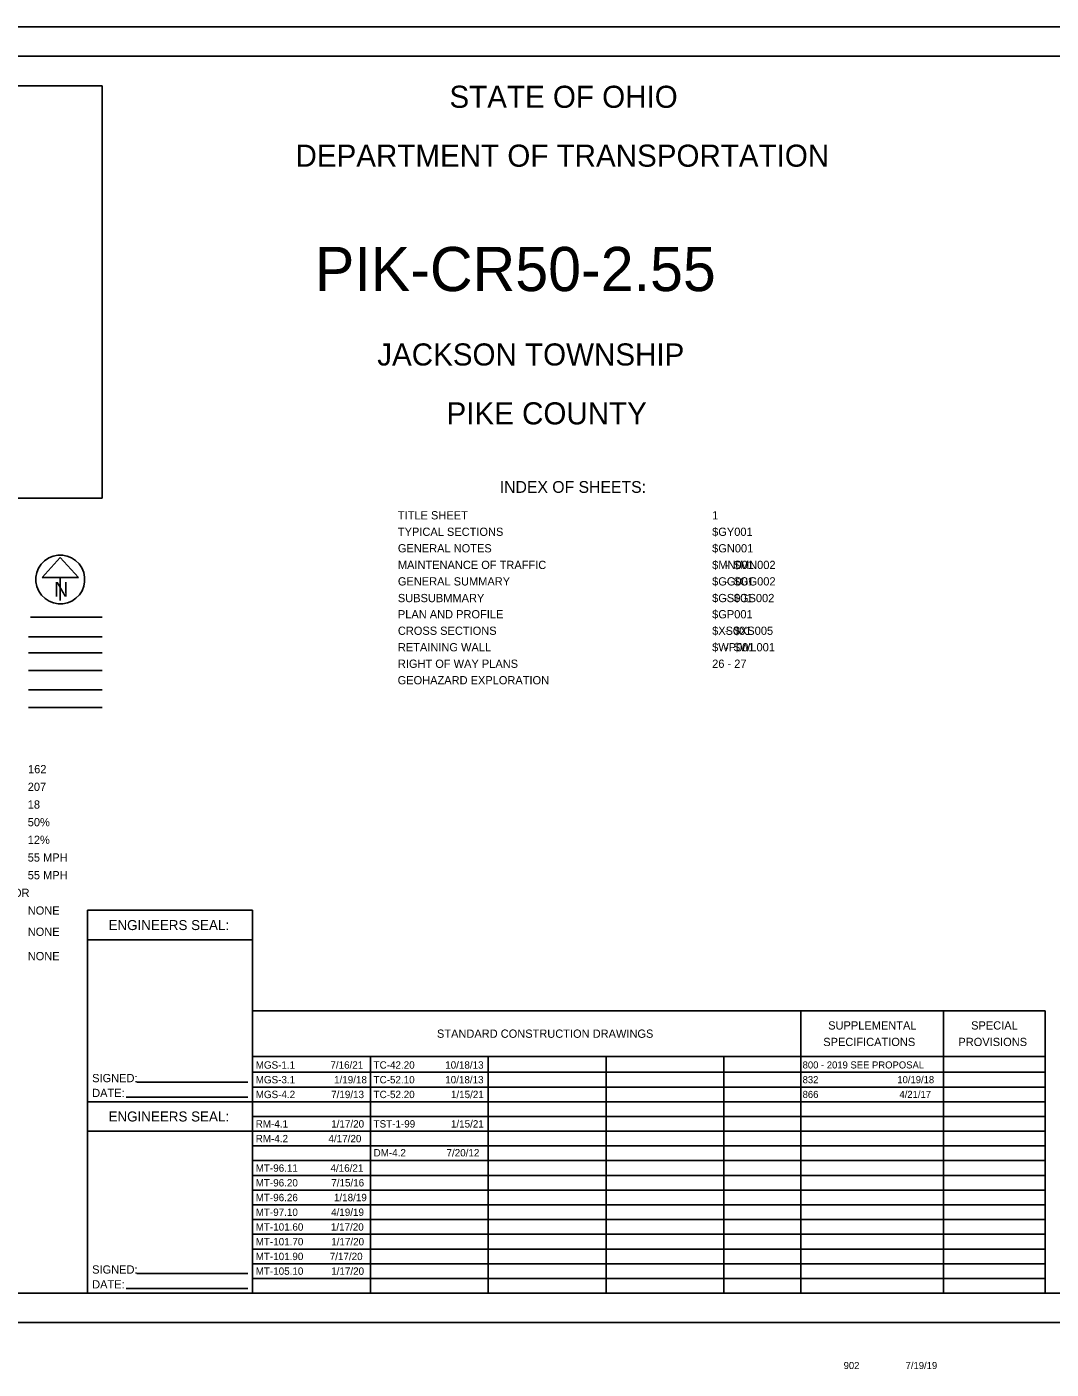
# Model space of a CAD drawing. Extents: x 1862092.2 to 1862141.4, y 420599.8 to 420643.6.
# Drawn here: x 1862105.2 to 1862122.58, y 420599.83 to 420622.62 of the extents above; entities that cross this region are included whole.
import ezdxf

# ---------------------------------------------------------------- set-up
doc = ezdxf.new("R2010")
doc.units = 0
for name, color, linetype in [('SH_Border', 7, 'Continuous'), ('SH_Cut_Line', 7, 'Continuous'), ('SH_Data', 7, 'Continuous')]:
    doc.layers.add(name, color=color, linetype=linetype)

msp = doc.modelspace()

# ---------------------------------------------------------------- linework, layer by layer
at = {"layer": 'SH_Border'}
msp.add_lwpolyline([(1862098.979, 420622.116), (1862130.479, 420622.116), (1862130.479, 420601.116), (1862098.979, 420601.116)], close=True, dxfattribs=at)
at = {"layer": 'SH_Cut_Line'}
msp.add_lwpolyline([(1862096.979, 420600.616), (1862130.979, 420600.616), (1862130.979, 420622.616), (1862096.979, 420622.616)], close=True, dxfattribs=at)
at = {"layer": 'SH_Data'}
for p, q in [((1862099.479, 420621.616), (1862106.479, 420621.616)), ((1862106.479, 420621.616), (1862106.479, 420614.616)), ((1862099.479, 420614.616), (1862106.479, 420614.616)), ((1862105.768, 420613.607), (1862105.461, 420613.265)), ((1862106.076, 420613.265), (1862105.768, 420613.607)), ((1862105.461, 420613.265), (1862106.076, 420613.265)), ((1862105.768, 420613.265), (1862105.768, 420612.879)), ((1862105.768, 420613.233), (1862105.768, 420613.233)), ((1862105.768, 420613.233), (1862105.768, 420613.233)), ((1862105.262, 420612.592), (1862106.479, 420612.592)), ((1862106.479, 420612.257), (1862105.229, 420612.257)), ((1862106.479, 420611.986), (1862105.229, 420611.986)), ((1862106.479, 420611.686), (1862105.229, 420611.686)), ((1862106.479, 420611.359), (1862105.229, 420611.359)), ((1862106.479, 420611.059), (1862105.229, 420611.059)), ((1862106.229, 420604.366), (1862106.229, 420607.616)), ((1862106.229, 420607.616), (1862109.029, 420607.616)), ((1862109.029, 420605.908), (1862109.029, 420607.616)), ((1862106.229, 420607.116), (1862109.029, 420607.116)), ((1862109.029, 420605.908), (1862122.479, 420605.908)), ((1862109.029, 420601.116), (1862109.029, 420605.908)), ((1862118.333, 420601.116), (1862118.333, 420605.908)), ((1862120.754, 420601.116), (1862120.754, 420605.908)), ((1862122.479, 420601.116), (1862122.479, 420605.908)), ((1862109.029, 420605.137), (1862122.479, 420605.137)), ((1862111.029, 420601.116), (1862111.029, 420605.137)), ((1862113.029, 420601.116), (1862113.029, 420605.137)), ((1862115.029, 420601.116), (1862115.029, 420605.137)), ((1862117.029, 420601.116), (1862117.029, 420605.137)), ((1862109.029, 420604.866), (1862122.479, 420604.866)), ((1862107.065, 420604.698), (1862108.95, 420604.698)), ((1862109.029, 420604.616), (1862122.479, 420604.616)), ((1862106.229, 420601.116), (1862106.229, 420604.366)), ((1862106.229, 420604.366), (1862109.029, 420604.366)), ((1862106.887, 420604.446), (1862108.95, 420604.446)), ((1862109.029, 420604.366), (1862122.479, 420604.366)), ((1862109.029, 420604.116), (1862122.479, 420604.116)), ((1862106.229, 420603.866), (1862109.029, 420603.866)), ((1862109.029, 420603.866), (1862122.479, 420603.866)), ((1862109.029, 420603.616), (1862122.479, 420603.616)), ((1862109.029, 420603.366), (1862122.479, 420603.366)), ((1862109.029, 420603.116), (1862122.479, 420603.116)), ((1862109.029, 420602.866), (1862122.479, 420602.866)), ((1862109.029, 420602.616), (1862122.479, 420602.616)), ((1862109.029, 420602.366), (1862122.479, 420602.366)), ((1862109.029, 420602.116), (1862122.479, 420602.116)), ((1862109.029, 420601.866), (1862122.479, 420601.866)), ((1862109.029, 420601.616), (1862122.479, 420601.616)), ((1862107.065, 420601.448), (1862108.95, 420601.448)), ((1862109.029, 420601.366), (1862122.479, 420601.366)), ((1862106.887, 420601.196), (1862108.95, 420601.196))]:
    msp.add_line(p, q, dxfattribs=at)
msp.add_arc((1862105.768, 420613.233), 0.415, 129.7798, 129.7633, dxfattribs=at)

# ---------------------------------------------------------------- texts
for s, height, p in [('STATE OF OHIO', 0.375, (1862112.371, 420621.241)), ('DEPARTMENT OF TRANSPORTATION', 0.375, (1862109.759, 420620.241)), ('PIK-CR50-2.55', 0.75, (1862110.089, 420618.129)), ('JACKSON TOWNSHIP', 0.375, (1862111.146, 420616.866)), ('PIKE COUNTY', 0.375, (1862112.321, 420615.866)), ('INDEX OF SHEETS:', 0.2, (1862113.224, 420614.704)), ('TITLE SHEET', 0.14, (1862111.496, 420614.253)), ('1', 0.14, (1862116.828, 420614.253)), ('TYPICAL SECTIONS', 0.14, (1862111.496, 420613.973)), ('$GY001', 0.14, (1862116.828, 420613.973)), ('GENERAL NOTES', 0.14, (1862111.496, 420613.693)), ('$GN001', 0.14, (1862116.828, 420613.693)), ('MAINTENANCE OF TRAFFIC', 0.14, (1862111.496, 420613.411)), ('$MN001', 0.14, (1862116.828, 420613.411)), ('-', 0.14, (1862117.041, 420613.411)), ('$MN002', 0.14, (1862117.196, 420613.411)), ('GENERAL SUMMARY', 0.14, (1862111.496, 420613.131)), ('$GG001', 0.14, (1862116.828, 420613.131)), ('-', 0.14, (1862117.041, 420613.131)), ('$GG002', 0.14, (1862117.196, 420613.131)), ('SUBSUBMMARY', 0.14, (1862111.496, 420612.848)), ('$GS001', 0.14, (1862116.828, 420612.848)), ('$GS002', 0.14, (1862117.196, 420612.848)), ('PLAN AND PROFILE', 0.14, (1862111.496, 420612.573)), ('$GP001', 0.14, (1862116.828, 420612.573)), ('-', 0.14, (1862117.041, 420612.848)), ('CROSS SECTIONS', 0.14, (1862111.496, 420612.293)), ('$XS001', 0.14, (1862116.828, 420612.293)), ('-', 0.14, (1862117.041, 420612.293)), ('$XS005', 0.14, (1862117.196, 420612.293)), ('RETAINING WALL', 0.14, (1862111.496, 420612.013)), ('$WP001', 0.14, (1862116.828, 420612.013)), ('-', 0.14, (1862117.041, 420612.013)), ('$WL001', 0.14, (1862117.196, 420612.013)), ('RIGHT OF WAY PLANS', 0.14, (1862111.496, 420611.733)), ('26 - 27', 0.14, (1862116.828, 420611.733)), ('GEOHAZARD EXPLORATION', 0.14, (1862111.492, 420611.453)), ('162', 0.14, (1862105.221, 420609.943)), ('207', 0.14, (1862105.216, 420609.643)), ('18', 0.14, (1862105.216, 420609.343)), ('50%', 0.14, (1862105.216, 420609.043)), ('12%', 0.14, (1862105.216, 420608.743)), ('55 MPH', 0.14, (1862105.216, 420608.443)), ('55 MPH', 0.14, (1862105.216, 420608.143)), ('DESIGN FUNCTIONAL CLASSIFICATION: 05 MAJOR COLLECTOR', 0.14, (1862099.473, 420607.843)), ('NONE', 0.14, (1862105.216, 420607.543)), ('ENGINEERS SEAL:', 0.17, (1862106.586, 420607.281)), ('NONE', 0.14, (1862105.216, 420607.183)), ('NONE', 0.14, (1862105.216, 420606.769)), ('SUPPLEMENTAL', 0.14, (1862118.797, 420605.592)), ('SPECIAL', 0.14, (1862121.222, 420605.592)), ('STANDARD CONSTRUCTION DRAWINGS', 0.14, (1862112.159, 420605.452)), ('SPECIFICATIONS', 0.14, (1862118.713, 420605.312)), ('PROVISIONS', 0.14, (1862121.006, 420605.312)), ('MGS-1.1', 0.125, (1862109.084, 420604.928)), ('7/16/21', 0.125, (1862110.351, 420604.928)), ('TC-42.20', 0.125, (1862111.084, 420604.928)), ('10/18/13', 0.125, (1862112.299, 420604.928)), ('800 - 2019 SEE PROPOSAL', 0.12, (1862118.363, 420604.931)), ('SIGNED:', 0.14, (1862106.309, 420604.698)), ('MGS-3.1', 0.125, (1862109.084, 420604.678)), ('1/19/18', 0.125, (1862110.413, 420604.678)), ('TC-52.10', 0.125, (1862111.084, 420604.678)), ('10/18/13', 0.125, (1862112.299, 420604.678)), ('832', 0.12, (1862118.363, 420604.681)), ('10/19/18', 0.12, (1862119.97, 420604.681)), ('DATE:', 0.14, (1862106.309, 420604.446)), ('MGS-4.2', 0.125, (1862109.084, 420604.428)), ('7/19/13', 0.125, (1862110.364, 420604.428)), ('TC-52.20', 0.125, (1862111.084, 420604.428)), ('1/15/21', 0.125, (1862112.396, 420604.428)), ('866', 0.12, (1862118.363, 420604.431)), ('4/21/17', 0.12, (1862120.006, 420604.431)), ('ENGINEERS SEAL:', 0.17, (1862106.586, 420604.031)), ('RM-4.1', 0.125, (1862109.084, 420603.928)), ('1/17/20', 0.125, (1862110.365, 420603.928)), ('TST-1-99', 0.125, (1862111.084, 420603.928)), ('1/15/21', 0.125, (1862112.396, 420603.928)), ('4/17/20', 0.125, (1862110.319, 420603.678)), ('RM-4.2', 0.125, (1862109.084, 420603.678)), ('DM-4.2', 0.125, (1862111.084, 420603.438)), ('7/20/12', 0.125, (1862112.321, 420603.438)), ('MT-96.11', 0.125, (1862109.084, 420603.178)), ('4/16/21', 0.125, (1862110.353, 420603.178)), ('MT-96.20', 0.125, (1862109.084, 420602.928)), ('7/15/16', 0.125, (1862110.366, 420602.928)), ('MT-96.26', 0.125, (1862109.084, 420602.678)), ('1/18/19', 0.125, (1862110.411, 420602.678)), ('MT-97.10', 0.125, (1862109.084, 420602.428)), ('4/19/19', 0.125, (1862110.363, 420602.428)), ('MT-101.60', 0.125, (1862109.084, 420602.178)), ('1/17/20', 0.125, (1862110.359, 420602.178)), ('MT-101.70', 0.125, (1862109.084, 420601.928)), ('1/17/20', 0.125, (1862110.365, 420601.928)), ('MT-101.90', 0.125, (1862109.084, 420601.678)), ('7/17/20', 0.125, (1862110.34, 420601.678)), ('SIGNED:', 0.14, (1862106.309, 420601.448)), ('MT-105.10', 0.125, (1862109.084, 420601.428)), ('1/17/20', 0.125, (1862110.365, 420601.428)), ('DATE:', 0.14, (1862106.309, 420601.196)), ('902', 0.12, (1862119.059, 420599.828)), ('7/19/19', 0.12, (1862120.111, 420599.828))]:
    msp.add_text(s, height=height, dxfattribs=at).set_placement(p)
msp.add_text('N', height=0.25, rotation=360, dxfattribs=at).set_placement((1862105.664, 420612.942))

doc.saveas('drawing.dxf')
